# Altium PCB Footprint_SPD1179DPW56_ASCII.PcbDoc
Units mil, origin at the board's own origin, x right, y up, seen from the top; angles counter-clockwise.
Board outline 6000 x 4000 mil, 2 copper layers (Top Layer, Bottom Layer); 1 components, 0 nets, 58 pads, 25 vias.
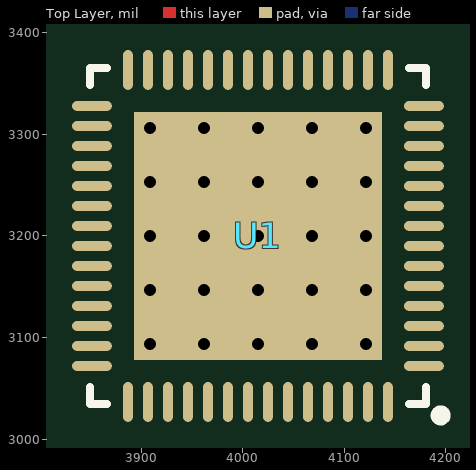
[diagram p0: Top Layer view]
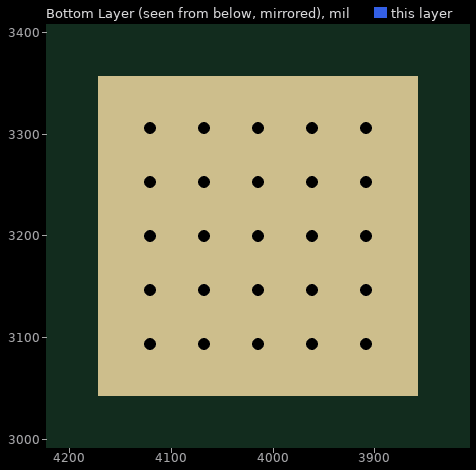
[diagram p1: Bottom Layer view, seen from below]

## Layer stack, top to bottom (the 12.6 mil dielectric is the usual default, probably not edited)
Top Solder: solder mask 0.4, Solder Resist, Dk 3.5
Top Layer: signal copper 1.4
Dielectric 1: dielectric 12.6, FR-4, Dk 4.8
Bottom Layer: signal copper 1.4
Bottom Solder: solder mask 0.4, Solder Resist, Dk 3.5

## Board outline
1000,1000 7000,1000 7000,5000 1000,5000

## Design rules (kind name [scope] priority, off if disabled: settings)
AssemblyTestPointUsage [All] p0: scope1count=1 scope1_0_kind=Board scope1_0_value=Board scope2count=1 scope2_0_kind=Board scope2_0_value=Board commentlength=0
AssemblyTestpoint [All] p0: scope1count=1 scope1_0_kind=Board scope1_0_value=Board scope2count=1 scope2_0_kind=Board scope2_0_value=Board commentlength=0
Clearance [All] p0: scope1count=1 scope1_0_kind=Board scope1_0_value=Board scope2count=1 scope2_0_kind=Board scope2_0_value=Board commentlength=0 gap=10
Clearance [All] p1: gap=10 ignorepadtopadclearanceinfootprint=FALSE except(0: Arc-Hole Track-Hole SMDPad-Hole THPad-Hole Via-Hole Fill-Hole Poly-Hole Region-Hole Text-Hole)
ComponentClearance [All] p0: scope1count=1 scope1_0_kind=Board scope1_0_value=Board scope2count=1 scope2_0_kind=Board scope2_0_value=Board commentlength=0 gap=10 collisioncheckmode=3
DiffPairsRouting [All] p0: scope1count=1 scope1_0_kind=Board scope1_0_value=Board scope2count=1 scope2_0_kind=Board scope2_0_value=Board commentlength=0
FabricationTestPointUsage [All] p0: scope1count=1 scope1_0_kind=Board scope1_0_value=Board scope2count=1 scope2_0_kind=Board scope2_0_value=Board commentlength=0 valid=0 allowmultiple=FALSE
FabricationTestpoint [All] p0: scope1count=1 scope1_0_kind=Board scope1_0_value=Board scope2count=1 scope2_0_kind=Board scope2_0_value=Board commentlength=0 side=3 testpointundercomponent=TRUE minsize=40 maxsize=100 preferedsize=60 minholesize=0 maxholesize=40 preferedholesize=32 testpointgrid=1
FanoutControl Fanout_BGA [All] p0 off: scope1count=1 scope1_0_kind=Board scope1_0_value=Board scope2count=1 scope2_0_kind=Board scope2_0_value=Board commentlength=69 // Protel DXP Scope 1 Expression Was: IsBGA   Fanout_BGA (Default Rule)
FanoutControl Fanout_LCC [All] p0 off: scope1count=1 scope1_0_kind=Board scope1_0_value=Board scope2count=1 scope2_0_kind=Board scope2_0_value=Board commentlength=69 // Protel DXP Scope 1 Expression Was: IsLCC   Fanout_LCC (Default Rule)
FanoutControl Fanout_SOIC [All] p0 off: scope1count=1 scope1_0_kind=Board scope1_0_value=Board scope2count=1 scope2_0_kind=Board scope2_0_value=Board commentlength=71 // Protel DXP Scope 1 Expression Was: IsSOIC   Fanout_SOIC (Default Rule)
FanoutControl Fanout_Small [All] p0 off: scope1count=1 scope1_0_kind=Board scope1_0_value=Board scope2count=1 scope2_0_kind=Board scope2_0_value=Board commentlength=84 // Protel DXP Scope 1 Expression Was: (CompPinCount < 5)   Fanout_Small (Default Rule)
FanoutControl Fanout_Default [All] p0: scope1count=1 scope1_0_kind=Board scope1_0_value=Board scope2count=1 scope2_0_kind=Board scope2_0_value=Board commentlength=30 // Fanout_Default (Default Rule)
Height [All] p0: scope1count=1 scope1_0_kind=Board scope1_0_value=Board scope2count=1 scope2_0_kind=Board scope2_0_value=Board commentlength=0
HoleSize [All] p0: scope1count=1 scope1_0_kind=Board scope1_0_value=Board scope2count=1 scope2_0_kind=Board scope2_0_value=Board commentlength=0 absolutevalues=TRUE maxlimit=100 minlimit=1 maxpercent=80.000 minpercent=20.000
HoleToHoleClearance [All] p0: scope1count=1 scope1_0_kind=Board scope1_0_value=Board scope2count=1 scope2_0_kind=Board scope2_0_value=Board commentlength=0
LayerPairs [All] p0: scope1count=1 scope1_0_kind=Board scope1_0_value=Board scope2count=1 scope2_0_kind=Board scope2_0_value=Board commentlength=0 enforce=TRUE
MinimumSolderMaskSliver [All] p0: scope1count=1 scope1_0_kind=Board scope1_0_value=Board scope2count=1 scope2_0_kind=Board scope2_0_value=Board commentlength=0
NetAntennae [All] p0: scope1count=1 scope1_0_kind=Board scope1_0_value=Board scope2count=1 scope2_0_kind=Board scope2_0_value=Board commentlength=0
PasteMaskExpansion [All] p0: scope1count=1 scope1_0_kind=Board scope1_0_value=Board scope2count=1 scope2_0_kind=Board scope2_0_value=Board commentlength=0 expansion=0
PlaneClearance [All] p0: scope1count=1 scope1_0_kind=Board scope1_0_value=Board scope2count=1 scope2_0_kind=Board scope2_0_value=Board commentlength=0 clearance=20
PlaneConnect [All] p0: scope1count=1 scope1_0_kind=Board scope1_0_value=Board scope2count=1 scope2_0_kind=Board scope2_0_value=Board commentlength=0 planeconnectstyle=Relief reliefexpansion=20 reliefentries=4 reliefconductorwidth=10 reliefairgap=10
PolygonConnect [All] p0: scope1count=1 scope1_0_kind=Board scope1_0_value=Board scope2count=1 scope2_0_kind=Board scope2_0_value=Board commentlength=0 connectstyle=Relief reliefconductorwidth=10 reliefentries=4 polygonreliefangle="90 Angle"
PolygonConnect [All] p1: connectstyle=Relief reliefconductorwidth=10 reliefentries=4 polygonreliefangle="90 Angle" airgapwidth=10
RoutingCorners [All] p0: scope1count=1 scope1_0_kind=Board scope1_0_value=Board scope2count=1 scope2_0_kind=Board scope2_0_value=Board commentlength=0 cornerstyle=45-Degree minsetback=100 maxsetback=100
RoutingLayers [All] p0: scope1count=1 scope1_0_kind=Board scope1_0_value=Board scope2count=1 scope2_0_kind=Board scope2_0_value=Board commentlength=0 top layer=Automatic bottom layer=Automatic
RoutingPriority [All] p0: scope1count=1 scope1_0_kind=Board scope1_0_value=Board scope2count=1 scope2_0_kind=Board scope2_0_value=Board commentlength=0
RoutingTopology [All] p0: scope1count=1 scope1_0_kind=Board scope1_0_value=Board scope2count=1 scope2_0_kind=Board scope2_0_value=Board commentlength=0 topology=Shortest
RoutingVias [All] p0: scope1count=1 scope1_0_kind=Board scope1_0_value=Board scope2count=1 scope2_0_kind=Board scope2_0_value=Board commentlength=0 holewidth=28 width=50 viastyle="Through Hole" minholewidth=28 minwidth=50 maxholewidth=28 maxwidth=50
RoutingVias [All] p1: holewidth=28 width=50 viastyle="Through Hole" minholewidth=28 minwidth=50 maxholewidth=28 maxwidth=50
ShortCircuit [All] p0: scope1count=1 scope1_0_kind=Board scope1_0_value=Board scope2count=1 scope2_0_kind=Board scope2_0_value=Board commentlength=0 allowed=FALSE
SilkToBoardRegionClearance [All] p0: scope1count=1 scope1_0_kind=Board scope1_0_value=Board scope2count=1 scope2_0_kind=Board scope2_0_value=Board commentlength=0
SilkToSilkClearance [All] p0: scope1count=1 scope1_0_kind=Board scope1_0_value=Board scope2count=1 scope2_0_kind=Board scope2_0_value=Board commentlength=0
SilkToSolderMaskClearance [All] p0 off: scope1count=1 scope1_0_kind=Board scope1_0_value=Board scope2count=1 scope2_0_kind=Board scope2_0_value=Board commentlength=44 // Protel DXP Scope 1 Expression Was: IsPad
SolderMaskExpansion [All] p0: scope1count=1 scope1_0_kind=Board scope1_0_value=Board scope2count=1 scope2_0_kind=Board scope2_0_value=Board commentlength=0 expansion=4
SolderMaskExpansion [All] p1: expansion=4 istentingtop=FALSE
UnRoutedNet [All] p0: scope1count=1 scope1_0_kind=Board scope1_0_value=Board scope2count=1 scope2_0_kind=Board scope2_0_value=Board commentlength=0
UnpouredPolygon [All] p0: scope1count=1 scope1_0_kind=Board scope1_0_value=Board scope2count=1 scope2_0_kind=Board scope2_0_value=Board commentlength=0
Width [All] p0: scope1count=1 scope1_0_kind=Board scope1_0_value=Board scope2count=1 scope2_0_kind=Board scope2_0_value=Board commentlength=0 maxlimit=10 minlimit=10 preferedwidth=10
Width [All] p1: maxlimit=10 minlimit=10 preferedwidth=10
30 further rules are at their usual default settings.

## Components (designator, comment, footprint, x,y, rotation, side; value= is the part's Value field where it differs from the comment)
U1 "" QFN-56-0.5_B 4178.39,3072.05 r180 top

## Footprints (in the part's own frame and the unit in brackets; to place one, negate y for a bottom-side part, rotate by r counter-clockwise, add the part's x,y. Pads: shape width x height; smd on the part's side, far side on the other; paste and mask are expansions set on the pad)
QFN-56-0.5_B [mm] "按高发封装修改意见"
  oval 1x0.25 smd: 1(0,0) 2(0,-0.5) 3(0,-1) 4(0,-1.5) 5(0,-2) 6(0,-2.5) 7(0,-3) 8(0,-3.5) 9(0,-4) 10(0,-4.5) 11(0,-5) 12(0,-5.5) 13(0,-6) 14(0,-6.5) 29(8.3,-6.5) 30(8.3,-6) 31(8.3,-5.5) 32(8.3,-5) 33(8.3,-4.5) 34(8.3,-4) 35(8.3,-3.5) 36(8.3,-3) 37(8.3,-2.5) 38(8.3,-2) 39(8.3,-1.5) 40(8.3,-1) 41(8.3,-0.5) 42(8.3,0)
  oval 0.25x1 smd: 15(0.9,-7.4) 16(1.4,-7.4) 17(1.9,-7.4) 18(2.4,-7.4) 19(2.9,-7.4) 20(3.4,-7.4) 21(3.9,-7.4) 22(4.4,-7.4) 23(4.9,-7.4) 24(5.4,-7.4) 25(5.9,-7.4) 26(6.4,-7.4) 27(6.9,-7.4) 28(7.4,-7.4) 43(7.4,0.9) 44(6.9,0.9) 45(6.4,0.9) 46(5.9,0.9) 47(5.4,0.9) 48(4.9,0.9) 49(4.4,0.9) 50(3.9,0.9) 51(3.4,0.9) 52(2.9,0.9) 53(2.4,0.9) 54(1.9,0.9) 55(1.4,0.9) 56(0.9,0.9)
  rect 6.2x6.2 smd: 57(4.15,-3.25)
  rect 8x8 smd far side: 57(4.15,-3.25)
  silkscreen extent -0.55,-7.45 8.35,1.36

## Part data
U1: library part U_SPD1179_QFN56, "32-bit ARM CM4 automotives MCU with HV power management, LIN and PDRV"

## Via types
v1: diameter 23.62, hole 11.81, Top Layer to Bottom Layer, tented top, 25 vias

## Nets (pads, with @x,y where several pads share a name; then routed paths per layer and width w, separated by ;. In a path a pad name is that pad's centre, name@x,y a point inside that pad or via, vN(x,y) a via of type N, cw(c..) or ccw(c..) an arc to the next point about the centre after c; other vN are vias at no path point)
pads on no net: U1.1 U1.2 U1.3 U1.4 U1.5 U1.6 U1.7 U1.8 U1.9 U1.10 U1.11 U1.12 U1.13 U1.14 U1.15 U1.16 U1.17 U1.18 U1.19 U1.20 U1.21 U1.22 U1.23 U1.24 U1.25 U1.26 U1.27 U1.28 U1.29 U1.30 U1.31 U1.32 U1.33 U1.34 U1.35 U1.36 U1.37 U1.38 U1.39 U1.40 U1.41 U1.42 U1.43 U1.44 U1.45 U1.46 U1.47 U1.48 U1.49 U1.50 U1.51 U1.52 U1.53 U1.54 U1.55 U1.56 U1.57
copper on no net:
  other v1: 3908.66,3093.66 3961.83,3093.66 4015,3093.66 4068.17,3093.66 4121.34,3093.66 3908.66,3146.83 3961.83,3146.83 4015,3146.83 4068.17,3146.83 4121.34,3146.83 3908.66,3200 3961.83,3200 4015,3200 4068.17,3200 4121.34,3200 3908.66,3253.17 3961.83,3253.17 4015,3253.17 4068.17,3253.17 4121.34,3253.17 3908.66,3306.34 3961.83,3306.34 4015,3306.34 4068.17,3306.34 4121.34,3306.34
